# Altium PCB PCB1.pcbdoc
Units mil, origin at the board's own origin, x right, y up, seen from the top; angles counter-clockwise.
Board outline 3149.61 x 1968.5 mil, 2 copper layers (Top Layer, Bottom Layer), stack 62.206 mil thick; 95 components, 72 nets, 376 pads, 43 vias.
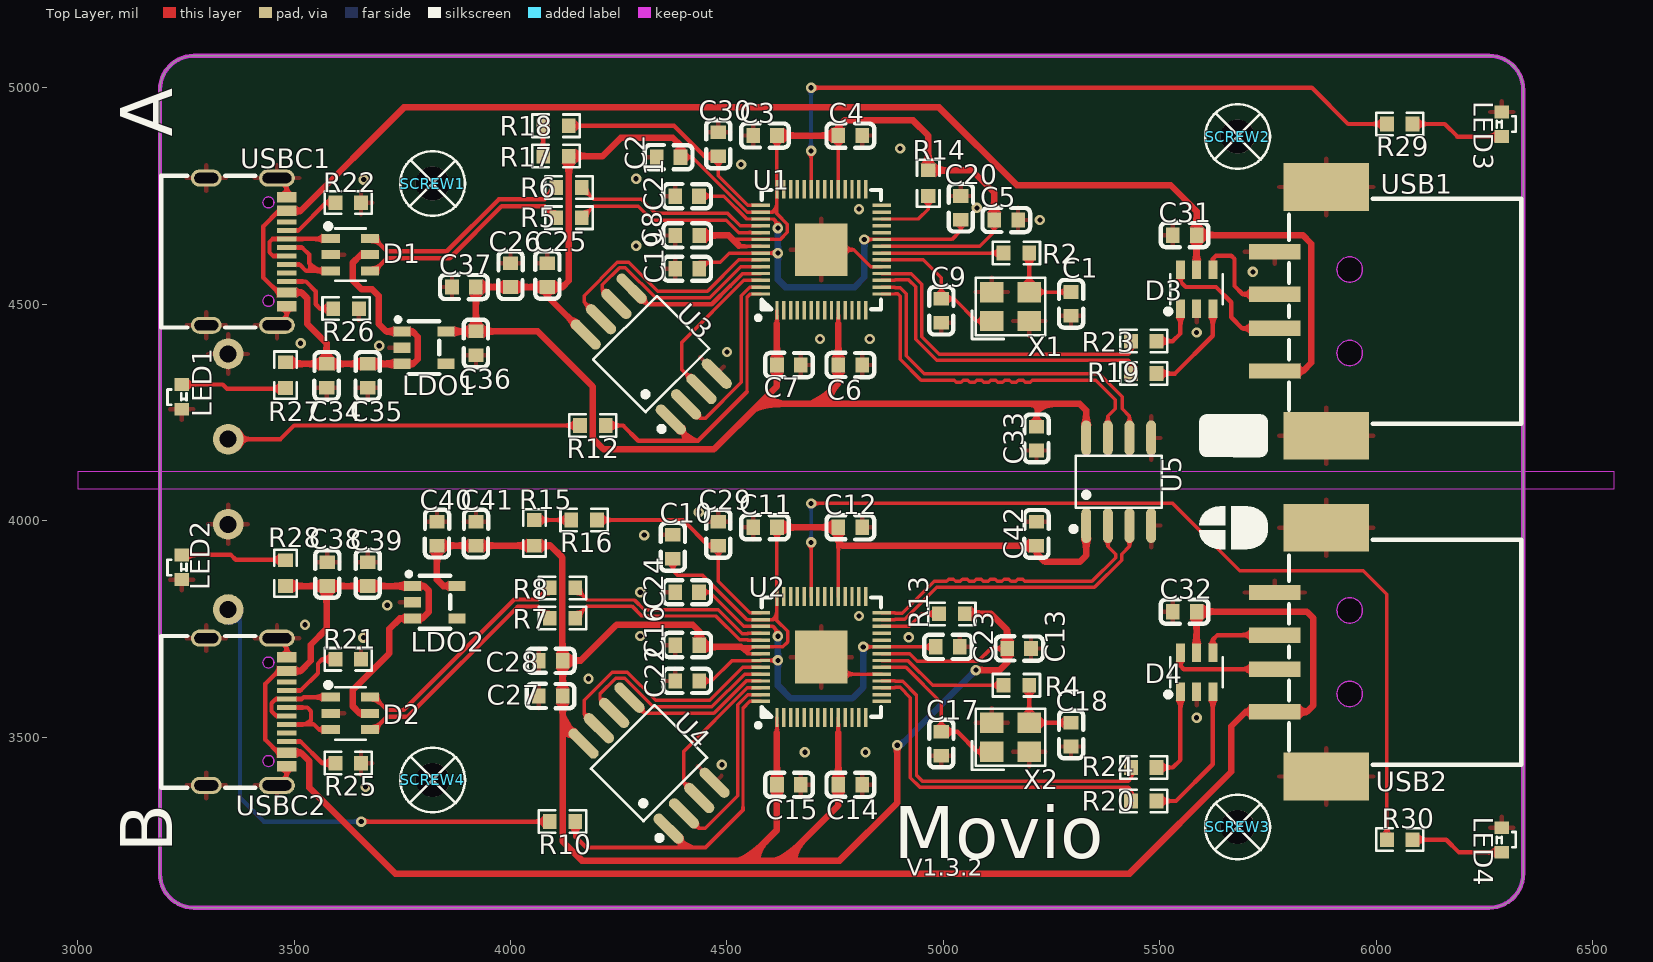
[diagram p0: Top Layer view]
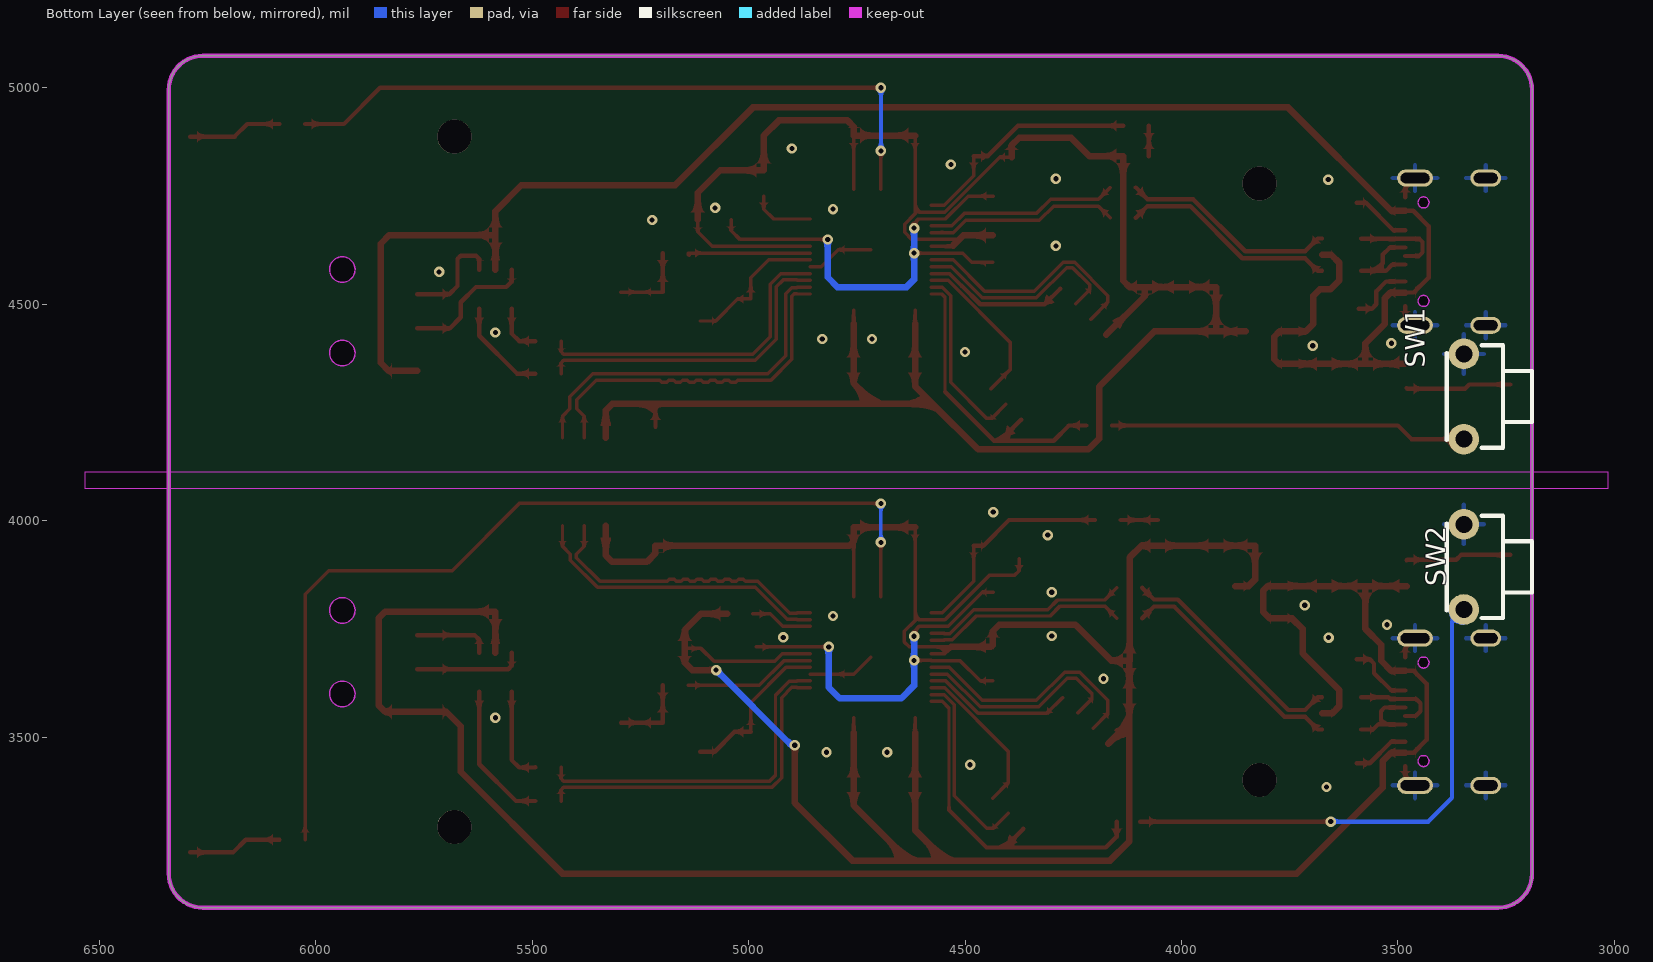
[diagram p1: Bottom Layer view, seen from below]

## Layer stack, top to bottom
Top Solder Mask Layer: solder mask 0.394, Dk 3.3
Top Layer: signal copper 1.379
Dielectric1: surface 59.449, FR4, Dk 4.5
Bottom Layer: signal copper 1.378
Bottom Solder Mask Layer: solder mask 0.394, Dk 3.3

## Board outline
3268.74,5074.45 ccw(c3268.74,4995.71) 3190,4995.71 3190,3184.69 ccw(c3268.74,3184.69) 3268.74,3105.94 6260.87,3105.94 ccw(c6260.87,3184.69) 6339.61,3184.69 6339.61,4995.71 ccw(c6260.87,4995.71) 6260.87,5074.45 3268.74,5074.45

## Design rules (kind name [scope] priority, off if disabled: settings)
BoardOutlineClearance copperThickness2oz_1 [All] p2 off: genericclearance=7.99 ignorepadtopadclearanceinfootprint=FALSE except(0: Arc-SplitContinuation Track-SplitContinuation SMDPad-SplitContinuation THPad-SplitContinuation Via-SplitContinuation Fill-SplitContinuation Region-SplitContinuation Poly-SplitContinuation Text-SplitContinuation Hole-SplitContinuation; 5.98: Arc-CutoutEdge SMDPad-CutoutEdge THPad-CutoutEdge Via-CutoutEdge Fill-CutoutEdge Region-CutoutEdge Text-CutoutEdge; 6.93: Hole-OutlineEdge Hole-CutoutEdge; 10: Poly-OutlineEdge Poly-CutoutEdge; 11.81: Arc-OutlineEdge Track-OutlineEdge SMDPad-OutlineEdge THPad-OutlineEdge Via-OutlineEdge Fill-OutlineEdge Region-OutlineEdge Text-OutlineEdge Track-CutoutEdge)
BoardOutlineClearance copperThickness1oz_1 [All] p4: genericclearance=4.02 ignorepadtopadclearanceinfootprint=FALSE except(0: Arc-SplitContinuation Track-SplitContinuation SMDPad-SplitContinuation THPad-SplitContinuation Via-SplitContinuation Fill-SplitContinuation Region-SplitContinuation Poly-SplitContinuation Text-SplitContinuation Hole-SplitContinuation; 6: SMDPad-CutoutEdge THPad-CutoutEdge Via-CutoutEdge Fill-CutoutEdge Region-CutoutEdge Text-CutoutEdge; 6.93: Hole-OutlineEdge Hole-CutoutEdge; 10: Poly-OutlineEdge Poly-CutoutEdge; 11.8: Arc-OutlineEdge Track-OutlineEdge SMDPad-OutlineEdge THPad-OutlineEdge Via-OutlineEdge Fill-OutlineEdge Region-OutlineEdge Text-OutlineEdge; 11.81: Arc-CutoutEdge Track-CutoutEdge)
Clearance copperThickness2oz [All] p1 off: gap=7.99 ignorepadtopadclearanceinfootprint=FALSE except(5.98: SMDPad-Track SMDPad-SMDPad THPad-Track SMDPad-THPad THPad-THPad Track-Via SMDPad-Via THPad-Via Via-Via Fill-Track Region-Track Fill-SMDPad Region-SMDPad Fill-THPad Region-THPad Fill-Via Region-Via Fill-Fill Fill-Region Region-Region Arc-Track Arc-SMDPad Arc-THPad Arc-Via Fill-Arc Region-Arc Arc-Arc Text-Track SMDPad-Text Text-THPad Text-Via Fill-Text Region-Text Arc-Text Text-Text; 6.93: Hole-Track Hole-SMDPad Hole-THPad Hole-Via Fill-Hole Region-Hole Hole-Arc Hole-Text; 10: Poly-Track Poly-SMDPad Poly-THPad Poly-Via Poly-Fill Poly-Region Poly-Poly Poly-Arc Poly-Text Poly-Hole)
Clearance copperThickness1oz [All] p3: gap=4.02 ignorepadtopadclearanceinfootprint=FALSE except(5.98: SMDPad-Track SMDPad-SMDPad THPad-Track SMDPad-THPad THPad-THPad Track-Via SMDPad-Via THPad-Via Via-Via Fill-Track Region-Track Fill-SMDPad Region-SMDPad Fill-THPad Region-THPad Fill-Via Region-Via Fill-Fill Fill-Region Region-Region; 6: Arc-Track Arc-SMDPad Arc-THPad Arc-Via Fill-Arc Region-Arc Arc-Arc Text-Track SMDPad-Text Text-THPad Text-Via Fill-Text Region-Text Arc-Text Text-Text; 6.93: Hole-Track Hole-SMDPad Hole-THPad Hole-Via Fill-Hole Region-Hole Hole-Arc Hole-Text; 10: Poly-Track Poly-SMDPad Poly-THPad Poly-Via Poly-Fill Poly-Region Poly-Poly Poly-Arc Poly-Text Poly-Hole)
Creepage creepage [All] p1: checkdistance=0 ignoreinternallayers=TRUE applytopolygonpour=TRUE
DiffPairsRouting differentialPair [All] p1: maxlimit=6 minlimit=6 mostfreqgap=6 toplayer_minwidth=5 toplayer_prefwidth=10 toplayer_maxwidth=100 toplayer_mingap=6 toplayer_prefgap=6 toplayer_maxgap=6 bottomlayer_minwidth=5 bottomlayer_prefwidth=10 bottomlayer_maxwidth=100 bottomlayer_mingap=6 bottomlayer_prefgap=6 bottomlayer_maxgap=6 maxuncoupledlength=10
HoleToHoleClearance otherClearance [All] p1: gap=11.81 allowstackedmicrovias=TRUE
Length netLength [All] p1: minlimit=0 maxlimit=0
MatchedLengths netLengthTolerance [All] p1: tolerance=1000
PasteMaskExpansion pasteMaskExpansion [All] p1: expansion=0
PlaneConnect innerPlane [All] p1: planeconnectstyle=Relief reliefexpansion=20 reliefentries=4 reliefconductorwidth=10 reliefairgap=10
PolygonConnect copperRegion [(InNet('GND_A') OR InNet('GND_B'))] p1: connectstyle=Relief reliefconductorwidth=10 reliefentries=4 polygonreliefangle="90 Angle" airgapwidth=10 via.connectstyle=Relief via.reliefconductorwidth=10 via.reliefentries=4 via.polygonreliefangle="90 Angle" via.airgapwidth=10
RoutingVias viaSize [All] p1: holewidth=12.01 width=24.02 viastyle="Through Hole" minholewidth=11.81 minwidth=19.68 maxholewidth=248.03 maxwidth=393.7
SolderMaskExpansion solderMaskExpansion [IsVia] p1: expansion=-1000 istentingtop=TRUE
SolderMaskExpansion solderMaskExpansion [All] p2: expansion=2 istentingtop=FALSE
Width copperThickness2oz_2 [All] p1 off: maxlimit=100 minlimit=8 preferedwidth=10
Width copperThickness1oz_2 [All] p2: maxlimit=100 minlimit=5 preferedwidth=10

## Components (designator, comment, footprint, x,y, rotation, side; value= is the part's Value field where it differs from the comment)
C1 "20pF" C0603#1 5295,4500.9 r270 top
C2 "2.2uF" C0603#2 4365,4840 r180 top
C3 "100nF" C0603#2 4587.97,4890 r0 top
C4 "100nF" C0603#2 4784.82,4890 r180 top
C5 "100nF" C0603#2 5145,4695 r180 top
C6 "100nF" C0603#2 4784.82,4360 r180 top
C7 "100nF" C0603#2 4643.09,4360 r180 top
C8 "100nF" C0603#2 4408.39,4659.18 r0 top
C9 "20pF" C0603#1 4995,4485 r270 top
C10 "2.2uF" C0603#2 4375,3940 r90 top
C11 "100nF" C0603#2 4587.97,3985 r0 top
C12 "100nF" C0603#2 4784.82,3985 r180 top
C13 "100nF" C0603#2 5175,3705 r180 top
C14 "100nF" C0603#2 4784.82,3390 r180 top
C15 "100nF" C0603#2 4643.09,3390 r180 top
C16 "100nF" C0603#2 4408.39,3712.76 r0 top
C17 "20pF" C0603#1 4995,3485 r270 top
C18 "20pF" C0603#1 5295,3505.91 r270 top
C19 "100nF" C0603#2 4408.39,4582.11 r0 top
C20 "100nF" C0603#2 5040.2,4722.9 r270 top
C21 "2.2uF" C0603#2 4407.78,4750 r180 top
C22 "100nF" C0603#2 4408.39,3630 r0 top
C23 "100nF" C0603#2 5010.2,3708.62 r180 top
C24 "2.2uF" C0603#2 4407.78,3835 r180 top
C25 "100nF" C0603#2 4085,4567.56 r270 top
C26 "2.2uF" C0603#2 4000,4567.56 r90 top
C27 "100nF" C0603#2 4092.74,3595 r0 top
C28 "2.2uF" C0603#2 4092.74,3676.67 r180 top
C29 "2.2uF" C0603#2 4480,3970 r90 top
C30 "2.2uF" C0603#2 4480,4870 r90 top
C31 "100nF" C0603#2 5557.44,4660 r0 top
C32 "100nF" C0603#2 5557.44,3790 r0 top
C33 "100nF" C0603#2 5215,4190 r270 top
C34 "2.2uF" C0603#1 3575,4335 r90 top
C35 "100nF" C0603#1 3670,4335 r90 top
C36 "2.2uF" C0603#1 3920,4410 r90 top
C37 "100nF" C0603#1 3892.44,4540 r0 top
C38 "2.2uF" C0603#1 3576.51,3876.83 r270 top
C39 "100nF" C0603#1 3670,3876.83 r270 top
C40 "2.2uF" C0603#1 3830,3970 r270 top
C41 "100nF" C0603#1 3920,3970 r270 top
C42 "100nF" C0603#2 5215.21,3970 r90 top
D1 "USBLC6-2SC6" SOT-23-6_L2.9-W1.6-P0.95-LS2.8-BL 3630,4614.74 r270 top locked
D2 "USBLC6-2SC6" SOT-23-6_L2.9-W1.6-P0.95-LS2.8-BL 3630,3555 r270 top locked
D3 "USBLC6-2SC6" SOT-23-6_L2.9-W1.6-P0.95-LS2.8-BL 5585,4535 r0 top locked
D4 "USBLC6-2SC6" SOT-23-6_L2.9-W1.6-P0.95-LS2.8-BL 5585,3650 r0 top locked
LDO1 "ME6211C33M5G-N" SOT-23-5_L3.0-W1.7-P0.95-LS2.8-BR 3800,4399.96 r180 top locked
LDO2 "ME6211C33M5G-N" SOT-23-5_L3.0-W1.7-P0.95-LS2.8-BR 3825,3811.87 r180 top locked
LED1 "YLED0602GSIDE" LED-SMD_L1.6-W1.1-R-RD_GREEN 3240,4286.31 r90 top
LED2 "YLED0602GSIDE" LED-SMD_L1.6-W1.1-R-RD_GREEN 3240,3892.61 r90 top
LED3 "YLED0602GSIDE" LED-SMD_L1.6-W1.1-R-RD_GREEN 6290,4916.02 r270 top
LED4 "YLED0602GSIDE" LED-SMD_L1.6-W1.1-R-RD_GREEN 6290,3262.48 r270 top
R2 "1kΩ" R0603 5168.65,4618.43 r180 top
R4 "1kΩ" R0603 5168.65,3620 r180 top
R5 "27R" R0603 4135,4700 r180 top
R6 "27R" R0603 4135,4770 r180 top
R7 "27R" R0603 4120,3775 r180 top
R8 "27R" R0603 4120,3845 r180 top
R10 "1kΩ" R0603 4120,3305 r0 top
R12 "1kΩ" R0603 4190,4220 r0 top
R13 "10kΩ" R0603 5019.66,3785 r0 top
R14 "10kΩ" R0603 4965,4780 r90 top
R15 "200Ω" R0603 4055,3972.1 r270 top
R16 "1Ω" R0603 4170,4001.76 r180 top
R17 "200Ω" R0603 4105,4842.44 r0 top
R18 "1Ω" R0603 4105,4912.56 r180 top
R19 "22Ω" R0603 5462.94,4340 r180 top
R20 "22Ω" R0603 5462.94,3352.49 r180 top
R21 "5.1kΩ" R0603 3625,3680 r0 top
R22 "5.1kΩ" R0603 3625,4735 r0 top
R23 "22Ω" R0603 5462.94,4415 r180 top
R24 "22Ω" R0603 5462.94,3430.19 r180 top
R25 "5.1kΩ" R0603 3625,3440 r0 top
R26 "5.1kΩ" R0603 3620,4490 r0 top
R27 "1kΩ" R0603 3480,4336.52 r90 top
R28 "1kΩ" R0603 3480,3878.93 r270 top
R29 "1K" R0603 6054.32,4916.83 r180 top locked
R30 "1K" R0603 6054.32,3263.22 r180 top locked
SCREW1 "" M2螺丝 3819.93,4779.17 r0 top
SCREW2 "" M2螺丝 5679.7,4887.59 r0 top
SCREW3 "" M2螺丝 5679.69,3292.8 r0 top
SCREW4 "" M2螺丝 3819.93,3401.23 r0 top
SW1 "TS-1096B-A1B2-D2" KEY-TH_L6.0-W3.3-P6.50 3347.48,4287.05 r90 bottom locked
SW2 "TS-1096B-A1B2-D2" KEY-TH_L6.0-W3.3-P6.50 3347.48,3893.35 r90 bottom locked
U1 "RP2040" LQFN-56_L7.0-W7.0-P0.4-EP 4717.89,4626.31 r90 top locked
U2 "RP2040" LQFN-56_L7.0-W7.0-P0.4-EP 4717.89,3685 r90 top locked
U3 "W25Q16JVSSIQ" SOIC-8_L5.3-W5.3-P1.27-LS8.0-BL 4325,4385 r45 top locked
U4 "W25Q16JVSSIQ" SOIC-8_L5.3-W5.3-P1.27-LS8.0-BL 4320,3440 r45 top locked
U5 "ADUM1201ARZ-RL7" SOIC-8_L4.9-W3.9-P1.27-LS6.0-BL 5405,4090.2 r0 top locked
USB1 "USB-234-BCW" USB-A-SMD_USB-234-BCW 5825,4483.9 r90 top locked
USB2 "USB-234-BCW" USB-A-SMD_USB-234-BCW 5825,3696.5 r90 top locked
USBC1 "TYPE-C16PIN" USB-C-SMD_TYPE-C16PIN 3390,4621.69 r270 top locked
USBC2 "TYPE-C16PIN" USB-C-SMD_TYPE-C16PIN 3390,3558.7 r270 top locked
X1 "12MHz" CRYSTAL-SMD_4P-L3.2-W2.5-BL 5155,4495 r0 top locked
X2 "12MHz" CRYSTAL-SMD_4P-L3.2-W2.5-BL 5155,3500 r0 top locked

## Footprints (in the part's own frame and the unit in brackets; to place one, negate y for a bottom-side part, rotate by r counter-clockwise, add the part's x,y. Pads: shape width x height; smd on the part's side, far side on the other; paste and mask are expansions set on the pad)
C0603#1 [mm]
  rect 0.8x0.9 smd paste+0 mask+0.051: 1(-0.7,0) 2(0.7,0)
  silkscreen extent -1.41,-0.71 1.39,0.72
C0603#2 [mm]
  rect 0.8x0.9 smd: 1(-0.7,0) 2(0.7,0)
  silkscreen extent -1.41,-0.71 1.39,0.72
CRYSTAL-SMD_4P-L3.2-W2.5-BL [mm]
  rect 1.4x1.2 smd paste+0 mask+0.051: 1(-1.1,-0.85) 2(1.1,-0.85) 3(1.1,0.85) 4(-1.1,0.85)
  silkscreen extent -2.26,-1.91 2.03,1.68
KEY-TH_L6.0-W3.3-P6.50 [mm]
  round 1.8 hole 1: 1(-2.5,0) 2(2.5,0)
  silkscreen extent -3,-4 3,1
LED-SMD_L1.6-W1.1-R-RD_GREEN [mm]
  rect 0.75x0.85 smd: 1(0.725,0) 2(-0.725,0)
  silkscreen extent -0.47,-0.29 0.43,0.83
LQFN-56_L7.0-W7.0-P0.4-EP [mm]
  rect 1.1x0.2 smd paste-100 mask+0.05: 1(-3.55,2.6) 2(-3.55,2.2) 3(-3.55,1.8) 4(-3.55,1.4) 5(-3.55,1) 6(-3.55,0.6) 7(-3.55,0.2) 8(-3.55,-0.2) 9(-3.55,-0.6) 10(-3.55,-1) 11(-3.55,-1.4) 12(-3.55,-1.8) 13(-3.55,-2.2) 14(-3.55,-2.6) 29(3.55,-2.6) 30(3.55,-2.2) 31(3.55,-1.8) 32(3.55,-1.4) 33(3.55,-1) 34(3.55,-0.6) 35(3.55,-0.2) 36(3.55,0.2) 37(3.55,0.6) 38(3.55,1) 39(3.55,1.4) 40(3.55,1.8) 41(3.55,2.2) 42(3.55,2.6)
  rect 0.2x1.1 smd paste-100 mask+0.05: 15(-2.6,-3.55) 16(-2.2,-3.55) 17(-1.8,-3.55) 18(-1.4,-3.55) 19(-1,-3.55) 20(-0.6,-3.55) 21(-0.2,-3.55) 22(0.2,-3.55) 23(0.6,-3.55) 24(1,-3.55) 25(1.4,-3.55) 26(1.8,-3.55) 27(2.2,-3.55) 28(2.6,-3.55) 43(2.6,3.55) 44(2.2,3.55) 45(1.8,3.55) 46(1.4,3.55) 47(1,3.55) 48(0.6,3.55) 49(0.2,3.55) 50(-0.2,3.55) 51(-0.6,3.55) 52(-1,3.55) 53(-1.4,3.55) 54(-1.8,3.55) 55(-2.2,3.55) 56(-2.6,3.55)
  rect 3.1x3.1 smd paste-100 mask+0.05: 57(0,0)
  silkscreen extent -4.13,-3.5 3.5,3.83
M2螺丝 [mm]
  round 2 hole 2: 1(0,0)
  silkscreen extent -1.9,-1.9 1.9,1.9
R0603 [mil]
  rect 31.75x34.02 smd paste-3937.01 mask+2: 1(-29.66,0) 2(29.66,0)
  silkscreen extent -55,-26 55,26
SOIC-8_L4.9-W3.9-P1.27-LS6.0-BL [mm]
  oval 0.588x2.045 smd: 1(-1.905,-2.57) 2(-0.635,-2.57) 3(0.635,-2.57) 4(1.905,-2.57) 5(1.905,2.57) 6(0.635,2.57) 7(-0.635,2.57) 8(-1.905,2.57)
  silkscreen extent -2.8,-2.92 2.53,1.52
SOIC-8_L5.3-W5.3-P1.27-LS8.0-BL [mm]
  oval 0.63x2.25 smd: 1(-1.905,-3.53) 2(-0.635,-3.53) 3(0.635,-3.53) 4(1.905,-3.53) 5(1.905,3.53) 6(0.635,3.53) 7(-0.635,3.53) 8(-1.905,3.53)
  silkscreen extent -2.82,-3.68 2.64,2.18
SOT-23-5_L3.0-W1.7-P0.95-LS2.8-BR [mm]
  rect 1x0.6 smd paste+0 mask+0.051: 1(1.3,-0.95) 2(1.3,0) 3(1.3,0.95) 4(-1.3,0.95) 5(-1.3,-0.95)
  silkscreen extent -0.9,-1.78 1.65,1.55
SOT-23-6_L2.9-W1.6-P0.95-LS2.8-BL [mil]
  rect 20.95x42.2 smd: 1(-37.4,-45.24) 2(0,-45.24) 3(37.4,-45.24) 4(37.4,45.24) 5(0,45.24) 6(-37.4,45.24)
  silkscreen extent -72,-57 61,35
USB-A-SMD_USB-234-BCW [mm]
  rect 0.9x3 smd: 1(-3.5,1.512) 2(-1,1.512) 3(1,1.512) 4(3.5,1.512)
  rect 2.8x5 smd: 5(-7.3,-1.512) 6(7.3,-1.512)
  Board Outline Layer circle w0.003: c-2.45,-2.888 r0.75
  Board Outline Layer circle w0.003: c2.45,-2.888 r0.75
  Board Outline Layer region: -2.45,-3.638 -2.776,-3.563 -3.036,-3.355 -3.181,-3.054 -3.181,-2.721 -3.036,-2.42 -2.776,-2.212 -2.45,-2.138 -2.45,-2.138 -2.125,-2.212 -1.864,-2.42 -1.719,-2.721 -1.719,-3.054 -1.864,-3.355 -2.125,-3.563 -2.45,-3.638
  Board Outline Layer region: -2.45,-3.638 -2.567,-3.628 -2.682,-3.601 -2.791,-3.556 -2.891,-3.494 -2.98,-3.418 -3.057,-3.328 -3.118,-3.228 -3.163,-3.119 -3.191,-3.005 -3.2,-2.888 -3.191,-2.77 -3.163,-2.656 -3.118,-2.547 -3.057,-2.447 -2.98,-2.357 -2.891,-2.281 -2.791,-2.219 -2.682,-2.174 -2.567,-2.147 -2.45,-2.138 -2.333,-2.147 -2.218,-2.174 -2.11,-2.219 -2.009,-2.281 -1.92,-2.357 -1.843,-2.447 -1.782,-2.547 -1.737,-2.656 -1.709,-2.77 -1.7,-2.888 -1.709,-3.005 -1.737,-3.119 -1.782,-3.228 -1.843,-3.328 -1.92,-3.418 -2.009,-3.494 -2.11,-3.556 -2.218,-3.601 -2.333,-3.628
  Board Outline Layer region: 2.45,-3.638 2.125,-3.563 1.864,-3.355 1.719,-3.054 1.719,-2.721 1.864,-2.42 2.125,-2.212 2.45,-2.138 2.45,-2.138 2.776,-2.212 3.036,-2.42 3.181,-2.721 3.181,-3.054 3.036,-3.355 2.776,-3.563 2.45,-3.638
  Board Outline Layer region: 2.45,-3.638 2.333,-3.628 2.218,-3.601 2.11,-3.556 2.009,-3.494 1.92,-3.418 1.843,-3.328 1.782,-3.228 1.737,-3.119 1.709,-3.005 1.7,-2.888 1.709,-2.77 1.737,-2.656 1.782,-2.547 1.843,-2.447 1.92,-2.357 2.009,-2.281 2.11,-2.219 2.218,-2.174 2.333,-2.147 2.45,-2.138 2.567,-2.147 2.682,-2.174 2.791,-2.219 2.891,-2.281 2.98,-2.357 3.057,-2.447 3.118,-2.547 3.163,-2.656 3.191,-2.77 3.2,-2.888 3.191,-3.005 3.163,-3.119 3.118,-3.228 3.057,-3.328 2.98,-3.418 2.891,-3.494 2.791,-3.556 2.682,-3.601 2.567,-3.628
  Multi-Layer board cut-out: -2.45,-3.638 -2.776,-3.563 -3.036,-3.355 -3.181,-3.054 -3.181,-2.721 -3.036,-2.42 -2.776,-2.212 -2.45,-2.138 -2.45,-2.138 -2.125,-2.212 -1.864,-2.42 -1.719,-2.721 -1.719,-3.054 -1.864,-3.355 -2.125,-3.563 -2.45,-3.638
  Multi-Layer board cut-out: 2.45,-3.638 2.125,-3.563 1.864,-3.355 1.719,-3.054 1.719,-2.721 1.864,-2.42 2.125,-2.212 2.45,-2.138 2.45,-2.138 2.776,-2.212 3.036,-2.42 3.181,-2.721 3.181,-3.054 3.036,-3.355 2.776,-3.563 2.45,-3.638
  silkscreen extent -6.6,-12.95 6.6,0.67
USB-C-SMD_TYPE-C16PIN [mm]
  oval 1x2.1 hole 0.6 slot 1.7 at 90 deg: 1(-4.32,1.787) 2(4.32,1.787)
  oval 1x1.8 hole 0.6 slot 1.4 at 90 deg: 3(-4.32,-2.362) 4(4.32,-2.362)
  rect 0.6x1.15 smd paste-100 mask+0.051: A1B12(-3.2,2.362) A4B9(-2.4,2.362) B1A12(3.2,2.362) B4A9(2.4,2.362)
  rect 0.3x1.15 smd paste-100 mask+0.051: A5(-1.25,2.362) A6(-0.25,2.362) A7(0.25,2.362) A8(1.25,2.362) B5(1.75,2.362) B6(0.75,2.362) B7(-0.75,2.362) B8(-1.75,2.362)
  Board Outline Layer circle w0.003: c2.89,1.288 r0.325
  Board Outline Layer circle w0.003: c-2.89,1.288 r0.325
  Board Outline Layer region: 2.89,1.613 3.031,1.581 3.144,1.491 3.207,1.36 3.207,1.216 3.144,1.085 3.031,0.995 2.89,0.963 2.89,0.963 2.749,0.995 2.636,1.085 2.573,1.216 2.573,1.36 2.636,1.491 2.749,1.581 2.89,1.613
  Board Outline Layer region: 2.89,1.613 2.968,1.604 3.041,1.576 3.106,1.531 3.157,1.473 3.194,1.403 3.213,1.327 3.213,1.249 3.194,1.173 3.157,1.103 3.106,1.045 3.041,1 2.968,0.972 2.89,0.963 2.812,0.972 2.739,1 2.675,1.045 2.623,1.103 2.586,1.173 2.567,1.249 2.567,1.327 2.586,1.403 2.623,1.473 2.675,1.531 2.739,1.576 2.812,1.604
  Board Outline Layer region: -2.89,1.613 -2.749,1.581 -2.636,1.491 -2.573,1.36 -2.573,1.216 -2.636,1.085 -2.749,0.995 -2.89,0.963 -2.89,0.963 -3.031,0.995 -3.144,1.085 -3.207,1.216 -3.207,1.36 -3.144,1.491 -3.031,1.581 -2.89,1.613
  Board Outline Layer region: -2.89,1.613 -2.812,1.604 -2.739,1.576 -2.675,1.531 -2.623,1.473 -2.586,1.403 -2.567,1.327 -2.567,1.249 -2.586,1.173 -2.623,1.103 -2.675,1.045 -2.739,1 -2.812,0.972 -2.89,0.963 -2.968,0.972 -3.041,1 -3.106,1.045 -3.157,1.103 -3.194,1.173 -3.213,1.249 -3.213,1.327 -3.194,1.403 -3.157,1.473 -3.106,1.531 -3.041,1.576 -2.968,1.604
  Multi-Layer board cut-out: 2.89,1.613 3.031,1.581 3.144,1.491 3.207,1.36 3.207,1.216 3.144,1.085 3.031,0.995 2.89,0.963 2.89,0.963 2.749,0.995 2.636,1.085 2.573,1.216 2.573,1.36 2.636,1.491 2.749,1.581 2.89,1.613
  Multi-Layer board cut-out: -2.89,1.613 -2.749,1.581 -2.636,1.491 -2.573,1.36 -2.573,1.216 -2.636,1.085 -2.749,0.995 -2.89,0.963 -2.89,0.963 -3.031,0.995 -3.144,1.085 -3.207,1.216 -3.207,1.36 -3.144,1.491 -3.031,1.581 -2.89,1.613
  silkscreen extent -4.45,-5 4.45,0.52

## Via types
v1: diameter 24.02, hole 12, Top Layer to Bottom Layer, 43 vias

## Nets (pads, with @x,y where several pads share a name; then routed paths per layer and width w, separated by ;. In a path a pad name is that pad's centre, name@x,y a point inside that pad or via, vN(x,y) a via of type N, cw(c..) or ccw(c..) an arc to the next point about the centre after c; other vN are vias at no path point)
1V1_A: C19.2 C20.2 C21.1 U1.23 U1.45 U1.50 | length 1089
  Top Layer w8: C21.1 4493.01,4750 4545.84,4697.17 U1.45 4607.94,4697.17 4617.72,4687.39 v1(4617.72,4676.07) ; C19.2@4435.95,4597.11 4484.14,4597.11 4505.46,4618.43 U1.50 v1(4617.72,4618.43) ; v1(4817.37,4649.93) U1.23 5019.93,4649.93 5040.2,4670.2 C20.2
  Bottom Layer w15: v1(4617.72,4676.07) v1(4617.72,4618.43) 4617.72,4557.28 4635,4540 4795,4540 4817.37,4562.37 v1(4817.37,4649.93)
1V1_B: C22.2 C23.2 C24.1 U2.23 U2.45 U2.50 | length 1031.1
  Top Layer w8: C24.1 4460,3835 4539.14,3755.86 U2.45 4606.34,3755.86 4617.77,3744.43 v1(4617.77,3733.11) ; C22.2 4465,3630 4512.12,3677.12 U2.50 4578.4,3677.39 v1@4621.25,3677.39 ; v1(4815,3708.62) U2.23 C23.2
  Bottom Layer w15: v1(4617.77,3733.11) v1(4617.77,3677.39) 4617.77,3619.2 4646.97,3590 4790,3590 4815,3615 v1(4815,3708.62)
$1N7129: R7.1 U2.47 | length 472.6
  Top Layer w8: R7.1 4177.66,3803 4280.49,3803 4303.49,3780 4474.45,3780 4529.2,3725.24 4547.6,3725.24 4548.47,3724.37 U2.47
$1N7131: R8.1 U2.46 | length 472.6
  Top Layer w8: R8.1 4177.66,3817 4286.29,3817 4309.29,3794 4480.24,3794 4535,3739.24 4547.6,3739.24 4548.47,3740.12 U2.46
$1N7133: R6.1 U1.46 | length 450.2
  Top Layer w8: R6.1 4191.66,4743 4302,4743 4335,4710 4502.17,4710 4530.74,4681.43 U1.46
$1N7134: R5.1 U1.47 | length 450.2
  Top Layer w8: R5.1 4191.66,4727 4295.37,4727 4328.37,4694 4498.37,4694 4526.95,4665.43 U1.47@4578.13,4665.43
$1N7164: D3.1 R23.1 | length 119.5
  Top Layer w10: R23.1 5530,4415 5547.6,4432.6 D3.1
$1N7165: D3.3 R19.1 | length 228.4
  Top Layer w10: R19.1 5535,4340 5622.4,4427.4 D3.3
$1N7176: D4.1 R24.1 | length 219.5
  Top Layer w10: R24.1 5492.79,3430 5530,3430 5547.6,3447.6 D4.1
$1N7177: D4.3 R20.1 | length 332.3
  Top Layer w10: R20.1 5537.48,3352.49 5622.4,3437.4 D4.3
$1N7196: C1.1 R2.1 X1.3 | length 186.7
  Top Layer w8: X1.3 C1.1
  Top Layer w10: X1.3 R2.1
$1N7203: C18.1 R4.1 X2.3 | length 183.2
  Top Layer w10: R4.1 X2.3 C18.1
$1N7209: R12.1 SW1.1 | length 825.9
  Top Layer w10: SW1.1 3468.62,4188.62 3500,4220 R12.1
$1N7288: R10.1 SW2.1 | length 1189.4
  Top Layer w10: v1(3655,3305) R10.1@4095.34,3305
  Bottom Layer w10: SW2.1 3375,3767.4 3375,3360 3430,3305 v1(3655,3305)
$1N7290: LED1.1 R27.1 | length 244.9
  Top Layer w10: LED1.1 3335.14,4314.86 3345,4305 3478.14,4305 R27.1
$1N7292: LED2.1 R28.1 | length 245.2
  Top Layer w10: LED2.1 3353.84,3921.16 3365,3910 3478.59,3910 R28.1
$1N7294: LED4.1 R30.1 | length 218.1
  Top Layer w10: R30.1 6161.78,3263.22 6191.06,3233.94 LED4.1
$1N7296: LED3.1 R29.1 | length 218.2
  Top Layer w10: R29.1 6158.17,4916.83 6187.52,4887.48 LED3.1
A+: R19.2 U1.17 | length 751.1
  Top Layer w8: U1.17 4887.31,4555.44 4888.18,4556.31 4920,4556.31 4936,4540.31 4936,4419.2 4984.2,4371 5413.32,4371 5413.82,4370.5 5427.62,4370.5 5433.28,4364.84 R19.2
A-: R23.2 U1.18 | length 751.1
  Top Layer w8: U1.18 4887.31,4571.19 4888.18,4570.31 4925.8,4570.31 4950,4546.11 4950,4425 4990,4385 5419.12,4385 5419.62,4384.5 5427.62,4384.5 5433.28,4390.16 R23.2
A_AVDD: C30.1 R18.1 U1.43 | length 546.3
  Top Layer w8: C30.1 4480,4796.99 4548.33,4728.67 U1.43
  Top Layer w10: R18.1 4377.44,4912.56 4447.56,4842.44 C30.1
A_CC1: R22.1 USBC1.A5 | length 138.9
  Top Layer w10: USBC1.A5 3510,4670.9 3574.1,4735 R22.1
A_CC2: R26.1 USBC1.B5 | length 150.9
  Top Layer w10: USBC1.B5 3527.21,4552.79 3550,4530 3550,4500 3560,4490 R26.1
A_DN: D1.1 USBC1.A7 USBC1.B7 | length 212.7
  Top Layer w10: USBC1.A7 3451.08,4611.85 3442.93,4620 3442.93,4644.15 3450,4651.22 USBC1.B7 3583.84,4651.22 D1.1
A_DP: D1.3 USBC1.A6 USBC1.B6 | length 211.6
  Top Layer w10: USBC1.B6 3512.84,4592.16 3527.66,4577.34 3552.66,4577.34 3535,4595 3535,4615 3518.47,4631.53 USBC1.A6 ; 3552.75,4577.34 D1.3
A_GPIO25: R29.2 U1.37 | length 1599.5
  Top Layer w8: U1.37 v1(4694.27,4854.51)
  Top Layer w10: v1(4694.27,5000.49) 5851.34,5000.49 5935,4916.83 R29.2
  Bottom Layer w10: v1(4694.27,4854.51) v1(4694.27,5000.49)
A_RUN: R14.1 U1.26 | length 147.1
  Top Layer w8: U1.26 4942.17,4697.17 4965,4720 R14.1
A_SCLK: U1.52 U3.6 | length 499.4
  Top Layer w8: U3.6 4211.68,4533.67 4211.68,4544.99 4251.69,4585 4265,4585 4335,4515 4460,4515 4531.94,4586.94 U1.52
A_SD0: U1.53 U3.5 | length 342.5
  Top Layer w8: 4508.52,4543.52 4536.19,4571.19 U1.53
  Top Layer w10: U3.5 4316.07,4500 4465,4500 4508.23,4543.23
A_SD1: U1.55 U3.2 | length 429.1
  Top Layer w8: U3.2 4438.32,4236.33 4449.63,4236.33 4533.26,4319.95 4533.26,4520.25 4552.69,4539.69 U1.55
A_SD2: U1.54 U3.3 | length 368.9
  Top Layer w8: U3.3 4395,4350.36 4395,4411.59 4538.84,4555.44 U1.54
A_SD3: U1.51 U3.7 | length 568.6
  Top Layer w8: U3.7 4170,4504.64 4170,4520.3 4246.72,4597.02 4272.98,4597.02 4340,4530 4455,4530 4527.69,4602.69 U1.51
A_SS: R12.2 U1.56 U3.1 | length 710
  Top Layer w8: 4546.27,4298.2 4546.27,4516.27 4553.95,4523.95 U1.56
  Top Layer w10: R12.2 4260,4220 4295,4185 4418.93,4185 ; U3.1 4418.93,4185 ; 4546.27,4298.2 4433.08,4185 4418.93,4185
A_USBDN: D1.6 R6.2 | length 503.3
  Top Layer w10: D1.6 3684.95,4652.14 3714.35,4622.74 3852.74,4622.74 3973,4743 4078.34,4743 R6.2
A_USBDP: D1.4 R5.2 | length 503.3
  Top Layer w10: D1.4 3684.95,4577.34 3714.35,4606.74 3859.37,4606.74 3979.63,4727 4078.34,4727 R5.2
A_VBUS: C31.2 C34.2 C35.2 D1.5 D3.5 LDO1.1 LDO1.3 R27.2 USB1.1 USBC1.A4B9 USBC1.B4A9 | length 4249
  Top Layer w10: R27.2 R27.2@3483.62,4362.56 ; USBC1.B4A9 3463.29,4527.2 3428.91,4561.58 3428.91,4680.57 3464.52,4716.18 USBC1.A4B9
  Top Layer w15: USBC1.B4A9 3517.23,4527.2 3530,4514.44 3530,4455 3575,4410 C34.2 ; USBC1.A4B9 3515,4716.18 3753.82,4955 4990,4955 5170,4775 5525,4775 5585,4715 C31.2 ; R27.2@3483.62,4362.56 C34.2 ; D1.5 3654.03,4614.74 3635,4595.72 3635,4555.65 3655.65,4535 3680,4535 3695,4520 3695,4455 3712.64,4437.36 LDO1.1 3773.25,4437.36 3785.61,4425 3785.61,4373.17 3775,4362.56 LDO1.3 C35.2 C34.2 ; D3.5 C31.2 ; USB1.1 5831.11,4346.11 5850,4365 5850,4640 5830,4660 C31.2
A_VREF: R17.1 R18.2 | length 70.1
  Top Layer w10: R17.1 R18.2
A_XIN: C9.1 U1.20 X1.1 | length 340.9
  Top Layer w8: U1.20 4953.44,4602.69 4995,4561.13 C9.1 5025,4512.56 5076.02,4461.53 X1.1
A_XOUT: R2.2 U1.21 | length 283.6
  Top Layer w8: U1.21 R2.2 ; R2.2@5137.42,4613.43 R2.2@5138.99,4615
B+: R20.2 U2.17 | length 808.3
  Top Layer w8: U2.17 4887.31,3614.13 4888.18,3615.01 4900,3615.01 4923.9,3591.11 4923.9,3406.3 4945.87,3384.34 5427.62,3384.34 5433.28,3378.68 R20.2
B-: R24.2 U2.18 | length 808.3
  Top Layer w8: U2.18 4887.31,3629.88 4888.18,3629.01 4905.8,3629.01 4937.9,3596.9 4937.9,3412.1 4951.66,3398.34 5427.62,3398.34 5433.28,3403.99 R24.2
B_AVDD: C29.1 R16.1 U2.43 | length 515.6
  Top Layer w8: C29.1 4480,3860 4552.64,3787.36 U2.43
  Top Layer w10: R16.1 4398.24,4001.76 4457.56,3942.44 C29.1
B_CC1: R21.1 USBC2.A5 | length 155.1
  Top Layer w10: USBC2.A5 3515,3607.91 3555,3647.91 3555,3670 3565,3680 R21.1
B_CC2: R25.1 USBC2.B5 | length 133
  Top Layer w10: USBC2.B5 3515,3489.8 3564.8,3440 R25.1
B_DN: D2.1 USBC2.A7 USBC2.B7 | length 201.4
  Top Layer w10: USBC2.A7 3458.61,3548.86 3447.56,3559.92 3447.56,3578.23 3457.56,3588.23 USBC2.B7 3518.23,3588.23 3522.4,3592.4 D2.1
B_DP: D2.3 USBC2.A6 USBC2.B6 | length 201.2
  Top Layer w10: USBC2.B6 3529.17,3529.17 ; USBC2.A6 3530.63,3568.54 3539.17,3560 3539.17,3539.17 3529.17,3529.17 ; D2.3 3557.4,3517.6 3545.83,3529.17 3529.17,3529.17
B_GPIO25: R30.2 U2.37 | length 2199.6
  Top Layer w8: U2.37 v1(4694.27,3950) ; v1(4694.27,4040) 5530,4040 5685,3885 5970,3885 6024.66,3830.34 R30.2
  Bottom Layer w8: v1(4694.27,3950) v1(4694.27,4040)
B_RUN: R13.1 U2.26 | length 144.4
  Top Layer w8: U2.26 4920.86,3755.86 4950,3785 R13.1
B_SCLK: U2.52 U4.6 | length 502.8
  Top Layer w8: U4.6 4206.68,3588.67 4206.68,3599.99 4242.94,3636.24 4263.76,3636.24 4329.96,3570.04 4465.04,3570.04 4540.63,3645.63 U2.52
B_SD0: U2.53 U4.5 | length 349.4
  Top Layer w8: U4.5 4311.07,3555 4470,3555 4544.88,3629.88 U2.53
B_SD1: U2.55 U4.2 | length 442.4
  Top Layer w8: U4.2 4434.64,3290 4450,3290 4525,3365 4525,3575 4548.38,3598.38 U2.55
B_SD2: U2.54 U4.3 | length 361.6
  Top Layer w8: U4.3 4400,3395.36 4400,3466.99 4547.14,3614.13 U2.54
B_SD3: U2.51 U4.7 | length 572.2
  Top Layer w8: U4.7 4170,3554.64 4170,3585 4235,3650 4270,3650 4335.12,3584.88 4459.88,3584.88 4536.38,3661.38 U2.51
B_SS: R10.2 U2.56 U4.1 | length 813.1
  Top Layer w8: 4537.02,3337.67 4537.02,3567.02 4552.64,3582.64 U2.56
  Top Layer w10: R10.2 4149.66,3270.34 4175,3245 4408.93,3245 ; U4.1 4408.93,3245 ; 4537.02,3337.67 4537.02,3331.72 4450.29,3245 4408.93,3245
B_USBDN: D2.6 R8.2 | length 544.1
  Top Layer w10: D2.6 3684.95,3592.4 3714.35,3563 3753.37,3563 4008.37,3818 4063.34,3818 R8.2
B_USBDP: D2.4 R7.2 | length 544.1
  Top Layer w10: D2.4 3684.95,3517.6 3714.35,3547 3762,3547 4017,3802 4063.34,3802 R7.2
B_VBUS: C32.2 C38.2 C39.2 D2.5 D4.5 LDO2.1 LDO2.3 R28.2 USB2.1 USBC2.A4B9 USBC2.B4A9 | length 4578.2
  Top Layer w10: USBC2.B4A9 3463.29,3464.21 3433.54,3493.96 3433.54,3623.44 3463.29,3653.19 USBC2.A4B9
  Top Layer w15: R28.2 C38.2 ; USBC2.B4A9 3515.79,3464.21 3535,3445 3535,3383.53 3733.53,3185 5430,3185 5665,3420 5665,3525 5698.71,3558.71 USB2.1 5840,3558.71 5855,3573.71 5855,3775 5840,3790 C32.2 D4.5 ; USBC2.A4B9 3515,3653.19 3538.48,3676.68 3538.48,3713.48 3575,3750 3575,3847.77 C38.2 ; D2.5 3651.82,3555 3635,3571.82 3635,3608.39 3720,3693.39 3720,3750 3744.47,3774.47 LDO2.3 3796,3774.47 3811.53,3790 3811.53,3838.47 3800.73,3849.27 LDO2.1 C39.2 C38.2
B_VREF: R15.1 R16.2 | length 85.3
  Top Layer w10: R15.1 R16.2
B_XIN: C17.1 U2.20 X2.1 | length 374.2
  Top Layer w8: U2.20 4913.62,3661.38 4995,3580 C17.1
  Top Layer w10: C17.1 5032.44,3512.56 5078.47,3466.53 X2.1
B_XOUT: R4.2 U2.21 | length 305
  Top Layer w8: U2.21 4917.88,3677.12 4975,3620 R4.2
GND_A: C1.2 C2.2 C3.1 C4.1 C5.1 C6.1 C7.1 C8.1 C9.2 C19.1 C20.1 C21.2 C25.1 C26.2 C30.2 C31.1 C33.2 C34.1 C35.1 C36.1 C37.1 D1.2 D3.2 LDO1.2 LED1.2 LED3.2 R22.2 R26.2 SW1.2 U1.19 U1.57 U3.4 U5.5 USB1.4 USB1.5 USB1.6 USBC1.1 USBC1.2 USBC1.3 USBC1.4 USBC1.A1B12 USBC1.B1A12 X1.2 X1.4 | length 263
  Top Layer w8: U1.57 4792.91,4626.31 4832.28,4586.94 U1.19
  Top Layer w10: USBC1.2 3483.01,4474.25 USBC1.B1A12 ; USBC1.1 3483.01,4769.13 USBC1.A1B12
  other v1: 4500,4390 3696.64,4404.45 3515,4410 4715,4420 4830,4420 5585,4435 5715,4575 4290,4635 5222.97,4694.89 4805,4720 5077.51,4722.9 3660.66,4788.27 4290,4790 4532.63,4823.21 4900,4860
GND_B: C10.2 C11.1 C12.1 C13.1 C14.1 C15.1 C16.1 C17.2 C18.2 C22.1 C23.1 C24.2 C27.1 C28.2 C29.2 C32.1 C38.1 C39.1 C40.1 C41.1 C42.2 D2.2 D4.2 LDO2.2 LED2.2 LED4.2 R21.2 R25.2 SW2.2 U2.19 U2.57 U4.4 U5.4 USB2.4 USB2.5 USB2.6 USBC2.1 USBC2.2 USBC2.3 USBC2.4 USBC2.A1B12 USBC2.B1A12 X2.2 X2.4 | length 263
  Top Layer w8: U2.57 4757.26,3645.63 U2.19
  Top Layer w10: USBC2.2 3483.01,3411.26 USBC2.B1A12 ; USBC2.1 3483.01,3706.14 USBC2.A1B12
  other v1: 3665,3385 4488.2,3436.42 4680,3465 4820,3465 5585,3545 4180,3635 3660,3730 4920,3730.61 4299.5,3733.69 3525,3760 4805,3780 3715,3805 4299.5,3834.89 4309.1,3966.78 4435,4020
KEY+: D3.4 USB1.3 | length 244.4
  Top Layer w10: D3.4 5622.4,4604.8 5630,4612.4 5665.2,4612.4 5672.6,4605 5672.6,4542.4 5691.73,4523.27 USB1.3
KEY-: D3.6 USB1.2 | length 310.9
  Top Layer w10: D3.6 5547.6,4552.4 5560,4540 5630,4540 5665,4505 5665,4470 5690.47,4444.53 USB1.2
MS+: D4.4 USB2.3 | length 177.3
  Top Layer w10: D4.4 5622.4,3725 5633.27,3735.87 USB2.3
MS-: D4.6 USB2.2 | length 251.4
  Top Layer w10: D4.6 5547.6,3665 5555.47,3657.13 USB2.2
UART_A_RX: U1.16 U5.6 | length 846.6
  Top Layer w8: U1.16 4887.31,4539.69 4888.18,4538.82 4900.8,4538.82 4914.66,4524.96 4914.66,4381.34 4956,4340 5359.63,4340 5413,4286.63 5413,4258.63 5430,4241.63 U5.6
UART_A_TX: U1.15 U5.7 | length 847.4
  Top Layer w8: U1.15 4887.31,4523.95 4888.18,4524.82 4895,4524.82 4900.66,4519.16 4900.66,4372.72 4948.37,4325 5024.58,4325 5029.58,4320 5040.58,4320 5045.58,4325 5056.58,4325 5061.58,4320 5072.58,4320 5077.58,4325 5088.58,4325 5093.58,4320 5104.58,4320 5109.58,4325 5120.58,4325 5125.58,4320 5136.58,4320 5141.58,4325 5152.58,4325 5157.58,4320 5168.58,4320 5173.58,4325 5184.58,4325 5189.58,4320 5200.58,4320 5205.58,4325 5352,4325 5397,4280 5397,4258.63 5380,4241.63 U5.7
UART_B_RX: U2.28 U5.2 | length 700.4
  Top Layer w8: U2.28 4887.31,3787.36 4888.18,3786.49 4905,3786.49 4978.52,3860 5007.22,3860 5012.22,3865 5023.22,3865 5028.22,3860 5039.22,3860 5044.22,3865 5055.22,3865 5060.22,3860 5071.22,3860 5076.22,3865 5087.22,3865 5092.22,3860 5103.22,3860 5108.22,3865 5119.22,3865 5124.22,3860 5135.22,3860 5140.22,3865 5151.22,3865 5156.22,3860 5167.22,3860 5172.22,3865 5183.22,3865 5188.22,3860 5343.24,3860 5398,3914.76 5398,3922.76 5380,3940.76 U5.2
UART_B_TX: U2.27 U5.3 | length 698.7
  Top Layer w8: U2.27 4887.31,3771.61 4888.18,3772.49 4910.8,3772.49 4984.31,3846 5349.04,3846 5412,3908.96 5412,3922.76 5430,3940.76 U5.3
VCC_A: C2.1 C3.2 C4.2 C5.2 C6.2 C7.2 C8.2 C25.2 C26.1 C33.1 C36.2 C37.2 LDO1.5 R14.2 R17.2 U1.1 U1.10 U1.22 U1.33 U1.42 U1.44 U1.48 U1.49 U3.8 U5.8 | length 5298.7
  Top Layer w8: C2.1 4420,4840 4547.08,4712.92 U1.44 4605.6,4712.92 4615.53,4722.84 ; 4516.75,4649.93 U1.48 4622.67,4649.93 4639.71,4666.97 4639.71,4685.29 4615.53,4709.47 4615.53,4722.84 ; 4529.25,4634.18 U1.49 ; 4615.53,4455 U1.1 ; C3.2 U1.42 4615.53,4722.84 ; 4757.26,4455 U1.10 ; U1.33 C4.2 ; U1.22 5084.18,4634.18 5117.44,4667.44 C5.2
  Top Layer w10: C33.1 5215,4250 5235,4270
  Top Layer w15: LDO1.5 3919.8,4437.36 C36.2 ; R17.2 4212.44,4842.44 4255,4885 4375,4885 4392.56,4867.44 C2.1 ; R17.2 4134.7,4554.7 4120,4540 C25.2 ; U3.8 4085,4518.93 C25.2 ; C8.2 4504.25,4659.18 4527.58,4635.85 ; 4615.53,4455 C7.2 4615.53,4310.53 4575,4270 ; C3.2 C4.2 4757.26,4910.59 4771.66,4925 4930,4925 4965,4890 R14.2 5065.34,4809.66 5117.44,4757.56 C5.2 ; 4757.26,4455 C6.2 4757.26,4317.26 4710,4270 ; U5.8 5330,4255 5315,4270 5235,4270 4710,4270 ; C36.2 C37.2 C26.1 C25.2 ; C36.2 4062.44,4437.56 4190,4310 4190,4190 4215,4165 4470,4165 4575,4270 ; 4575,4270 4710,4270
VCC_B: C10.1 C11.2 C12.2 C13.2 C14.2 C15.2 C16.2 C27.2 C28.1 C40.2 C41.2 C42.1 LDO2.5 R13.2 R15.2 U2.1 U2.10 U2.22 U2.33 U2.42 U2.44 U2.48 U2.49 U4.8 U5.1 | length 5935.3
  Top Layer w8: C10.1 4375,3885 4385.66,3874.34 4443.58,3874.34 4546.31,3771.61 U2.44 4606.61,3771.61 4615.53,3780.53 ; U2.49 4547.13,3692.87 4531.38,3708.62 U2.48 4628.62,3708.62 4640,3720 4640,3745 4615.53,3769.47 4615.53,3780.53 ; 4615.53,3510 U2.1 ; C11.2 U2.42 4615.53,3780.53 ; 4757.26,3510 U2.10 ; U2.33 4757.26,3952.74 ; U2.22 4922.13,3692.87 4940,3675 5080,3675 5110,3705 C13.2
  Top Layer w15: LDO2.5 3845,3849.27 3830,3864.27 C40.2 C41.2 R15.2 4092.56,3942.44 4120,3915 C28.1@4120,3676.97 ; U4.8 4120.3,3533.63 ; 4531.38,3708.62 4440.09,3708.62 C16.2 4435.95,3745 4420.95,3760 4245,3760 4161.67,3676.67 C28.1 C27.2 4120.3,3533.63 ; 4615.53,3510 C15.2 4615.53,3285.53 4545,3215 ; C11.2 C12.2 4757.26,3952.74 4767.56,3942.44 C42.1 5215.21,3924.79 5235,3905 5315,3905 5330,3920 U5.1 ; 4757.26,3510 C14.2 4757.26,3342.26 4630,3215 ; v1(4893.21,3481.22) 4893.21,3348.21 4760,3215 4630,3215 ; R13.2 5110,3785 5147.44,3747.56 C13.2 5147.44,3672.44 5130,3655 v1(5075,3655) ; 4120.3,3533.63 4120.3,3259.7 4165,3215 4545,3215 ; 4545,3215 4630,3215
  Bottom Layer w15: v1(4893.21,3481.22) 4901.22,3481.22 v1(5075,3655)
pads on no net: LDO1.4 LDO2.4 SCREW1.1 SCREW2.1 SCREW3.1 SCREW4.1 U1.2 U1.3 U1.4 U1.5 U1.6 U1.7 U1.8 U1.9 U1.11 U1.12 U1.13 U1.14 U1.24 U1.25 U1.27 U1.28 U1.29 U1.30 U1.31 U1.32 U1.34 U1.35 U1.36 U1.38 U1.39 U1.40 U1.41 U2.2 U2.3 U2.4 U2.5 U2.6 U2.7 U2.8 U2.9 U2.11 U2.12 U2.13 U2.14 U2.15 U2.16 U2.24 U2.25 U2.29 U2.30 U2.31 U2.32 U2.34 U2.35 U2.36 U2.38 U2.39 U2.40 U2.41 USBC1.A8 USBC1.B8 USBC2.A8 USBC2.B8

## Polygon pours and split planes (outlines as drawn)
GND_A on Top Layer (solid, remove dead copper, pour order 0): 3100,5105 3100,4113.82 6380.23,4113.82 6380.23,5105
GND_B on Top Layer (solid, remove dead copper, pour order 2): 3136.2,4074.45 3136.2,3025 6390,3025 6390,4074.45
GND_A on Bottom Layer (solid, remove dead copper, pour order 4): 3046.51,5115 3046.51,4113.82 6460,4113.82 6460,5115
GND_B on Bottom Layer (solid, remove dead copper, pour order 6): 3075,4074.45 3075,3000 6470,3000 6470,4074.45

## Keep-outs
Top Layer:
  region: 3000,4113.82 3000,4074.45 6550,4074.45 6550,4113.82
Bottom Layer:
  region: 3015,4113.82 3015,4074.45 6532.22,4074.45 6532.22,4113.82
Board Outline Layer:
  the board outline again, w10

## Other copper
Top Layer:
  drawing of 262 lines, arcs and shapes, not listed
Bottom Layer:
  region net $1N7288: 3378.54,3770.94 3371.46,3763.87 3370.88,3764.21 3370.07,3764.36 3367.83,3764.13 3364.89,3763.4 3361.42,3762.38 3357.57,3761.27 3353.48,3760.29 3349.33,3759.65 3347.28,3759.52 3345.26,3759.56 3382.84,3797.14 3382.88,3795.13 3382.75,3793.07 3382.11,3788.92 3381.13,3784.84 3380.02,3780.98 3379,3777.51 3378.27,3774.57 3378.05,3772.33 3378.19,3771.52
  region net 1V1_A: 4625.22,4602.08 4610.22,4602.08 4610.15,4604.64 4609.93,4607.04 4609.47,4609.06 4609.13,4609.86 4608.71,4610.48 4626.72,4610.48 4626.3,4609.86 4625.97,4609.06 4625.51,4607.04 4625.28,4604.64
  region net 1V1_A: 4610.22,4634.77 4625.22,4634.77 4625.28,4632.22 4625.51,4629.82 4625.97,4627.79 4626.3,4626.99 4626.72,4626.37 4608.71,4626.37 4609.13,4626.99 4609.47,4627.79 4609.93,4629.82 4610.15,4632.22
  region net 1V1_A: 4824.87,4633.58 4809.87,4633.58 4809.81,4636.14 4809.58,4638.54 4809.12,4640.56 4808.78,4641.36 4808.37,4641.98 4826.38,4641.98 4825.96,4641.36 4825.62,4640.56 4825.16,4638.54 4824.93,4636.14
  region net 1V1_A: 4625.22,4659.73 4610.22,4659.73 4610.15,4662.28 4609.93,4664.69 4609.47,4666.71 4609.13,4667.51 4608.71,4668.13 4626.72,4668.13 4626.3,4667.51 4625.97,4666.71 4625.51,4664.69 4625.28,4662.28
  region net A_GPIO25: 4689.27,4870.86 4699.27,4870.86 4699.34,4869.54 4699.55,4868.36 4700.35,4866.3 4701.61,4864.42 4703.27,4862.45 4685.26,4862.45 4686.93,4864.42 4688.19,4866.3 4688.99,4868.36 4689.2,4869.54
  region net A_GPIO25: 4699.27,4984.14 4689.27,4984.14 4689.2,4985.46 4688.99,4986.64 4688.19,4988.7 4686.93,4990.58 4685.26,4992.55 4703.27,4992.55 4701.61,4990.58 4700.35,4988.7 4699.55,4986.64 4699.34,4985.46
  region net 1V1_B: 4625.27,3716.76 4610.27,3716.76 4610.21,3719.32 4609.98,3721.72 4609.52,3723.75 4609.19,3724.55 4608.77,3725.17 4626.78,3725.17 4626.36,3724.55 4626.02,3723.75 4625.56,3721.72 4625.33,3719.32
  region net 1V1_B: 4822.5,3692.27 4807.5,3692.27 4807.44,3694.83 4807.21,3697.23 4806.75,3699.25 4806.41,3700.05 4805.99,3700.68 4824.01,3700.68 4823.59,3700.05 4823.25,3699.25 4822.79,3697.23 4822.56,3694.83
  region net $1N7288: 3638.65,3300 3638.65,3310 3639.97,3310.07 3641.14,3310.28 3643.2,3311.08 3645.09,3312.34 3647.06,3314.01 3647.06,3295.99 3645.09,3297.66 3643.2,3298.92 3641.14,3299.72 3639.97,3299.93
  region net B_GPIO25: 4690.27,3966.35 4698.27,3966.35 4698.38,3964.98 4698.68,3963.8 4699.17,3962.74 4699.8,3961.78 4701.4,3959.94 4703.27,3957.94 4685.26,3957.94 4687.13,3959.94 4688.73,3961.78 4689.36,3962.74 4689.85,3963.8 4690.16,3964.98
  region net B_GPIO25: 4698.27,4023.65 4690.27,4023.65 4690.16,4025.02 4689.85,4026.2 4689.36,4027.26 4688.73,4028.22 4687.13,4030.06 4685.26,4032.06 4703.27,4032.06 4701.4,4030.06 4699.8,4028.22 4699.17,4027.26 4698.68,4026.2 4698.38,4025.02
  region net VCC_B: 4906.02,3496.62 4910.41,3479.81 4909.49,3479.02 4908.55,3478.43 4906.69,3477.54 4904.93,3476.56 4904.14,3475.85 4903.43,3474.91 4899.03,3491.72 4899.57,3491.65 4900.28,3491.87 4902.06,3493.02 4904.07,3494.75
  region net 1V1_B: 4610.27,3693.74 4625.27,3693.74 4625.33,3691.18 4625.56,3688.78 4626.02,3686.76 4626.36,3685.96 4626.78,3685.33 4608.77,3685.33 4609.19,3685.96 4609.52,3686.76 4609.98,3688.78 4610.21,3691.18
  region net 1V1_B: 4625.27,3661.04 4610.27,3661.04 4610.21,3663.6 4609.98,3666 4609.52,3668.03 4609.19,3668.83 4608.77,3669.45 4626.78,3669.45 4626.36,3668.83 4626.02,3668.03 4625.56,3666 4625.33,3663.6
  region net VCC_B: 5068.74,3638.14 5058.14,3648.74 5059.9,3650.6 5061.44,3652.46 5062.54,3654.21 5062.87,3655.02 5063.02,3655.75 5075.75,3643.02 5075.02,3642.87 5074.21,3642.54 5072.46,3641.44 5070.6,3639.9

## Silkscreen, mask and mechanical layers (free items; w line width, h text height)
Top Silkscreen Layer:
  drawing of 15 lines, arcs and shapes, not listed
  text "A" at 3218.11,4886.97 h120 r90
  text "B" at 3218.12,3233.43 h120 r90
  text "Movio" at 4885,3220 h120
  text "V1.3.2" at 4915.58,3180 h40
